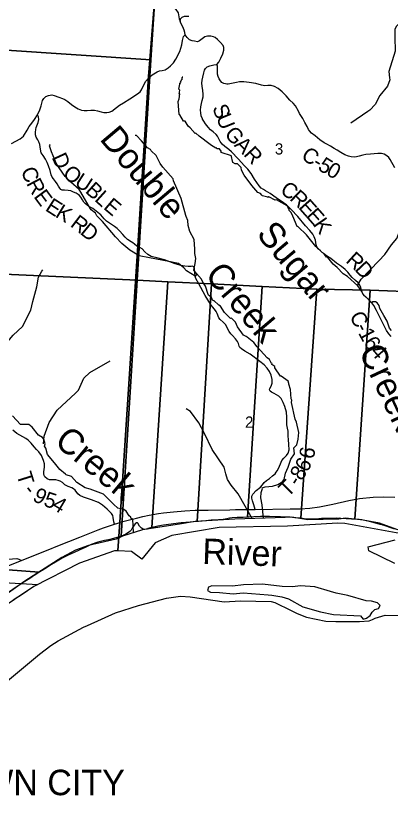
# Model space of a CAD drawing. Extents: x 1878108 to 2183446, y 146837 to 508383.
# Drawn here: x 2033633 to 2040993, y 212319 to 228134 of the extents above; entities that cross this region are included whole.
import ezdxf

# ---------------------------------------------------------------- set-up
doc = ezdxf.new("R2010")
doc.units = 0
for name, color, linetype in [('GM_X_Corporation', 7, 'Continuous'), ('GM_X_Corporation_Text', 7, 'Continuous'), ('GM_X_County', 7, 'Continuous'), ('GM_X_County_Road', 7, 'Continuous'), ('GM_X_County_Road_Text', 7, 'Continuous'), ('GM_X_Major_River', 7, 'Continuous'), ('GM_X_Major_River_Text', 7, 'Continuous'), ('GM_X_Minor_River', 7, 'Continuous'), ('GM_X_Minor_River_Text', 7, 'Continuous'), ('GM_X_Section', 7, 'Continuous'), ('GM_X_Section_Text', 7, 'Continuous'), ('GM_X_State_Route', 7, 'Continuous'), ('GM_X_Township', 7, 'Continuous'), ('GM_X_Township_Road', 7, 'Continuous'), ('GM_X_Township_Road_Text', 7, 'Continuous')]:
    doc.layers.add(name, color=color, linetype=linetype)

msp = doc.modelspace()

# ---------------------------------------------------------------- linework, layer by layer
at = {"layer": 'GM_X_Corporation'}
msp.add_lwpolyline([(2028815, 217287), (2034057, 216976), (2034022, 216959), (2033981, 216937), (2033944, 216913), (2033857, 216855), (2033789, 216810), (2033711, 216759), (2033635, 216707), (2033575, 216668)], dxfattribs=at)
at = {"layer": 'GM_X_County'}
for points in [[(2041168, 217981), (2040086, 218175), (2039954, 218181), (2038960, 218124), (2037622, 218100), (2036688, 217942), (2036361, 217795), (2036102, 217475), (2035896, 217629), (2035631, 217639), (2035563, 217641), (2034879, 217399), (2033979, 216936), (2033237, 216441)], [(2041068, 217391), (2040557, 217640), (2040547, 217716), (2041076, 217853)]]:
    msp.add_lwpolyline(points, dxfattribs=at)
at = {"layer": 'GM_X_County_Road'}
for points in [[(2037577, 227184), (2037613, 227229), (2037653, 227309), (2037694, 227392), (2037713, 227464), (2037711, 227516), (2037698, 227554), (2037648, 227616), (2037586, 227673), (2037541, 227712), (2037507, 227730), (2037460, 227738), (2037392, 227742), (2037338, 227730), (2037286, 227691), (2037236, 227650), (2037193, 227631), (2037136, 227639), (2037089, 227647), (2037039, 227671), (2036989, 227712), (2036956, 227764), (2036944, 227810), (2036935, 227860), (2036923, 227890), (2036904, 227924), (2036869, 227992), (2036853, 228035), (2036868, 228085), (2036897, 228115), (2036941, 228132), (2037023, 228135)], [(2036335, 227002), (2036401, 227041), (2036447, 227058), (2036502, 227067), (2036561, 227080), (2036619, 227117), (2036663, 227157), (2036722, 227215), (2036769, 227288), (2036845, 227438), (2036886, 227573), (2036903, 227657), (2036922, 227733), (2036956, 227764)], [(2037295, 226108), (2037291, 226116), (2037269, 226178), (2037262, 226233), (2037256, 226286), (2037261, 226354), (2037272, 226419), (2037289, 226480), (2037305, 226551), (2037306, 226605), (2037299, 226677), (2037284, 226762), (2037282, 226815), (2037288, 226878), (2037302, 226936), (2037318, 227020), (2037332, 227073), (2037354, 227107), (2037386, 227136), (2037434, 227159), (2037518, 227175), (2037577, 227184)], [(2041070, 225156), (2040978, 225321), (2040953, 225358), (2040916, 225393), (2040863, 225424), (2040807, 225436), (2040734, 225436), (2040590, 225426), (2040502, 225418), (2040442, 225405), (2040369, 225382), (2040318, 225370), (2040274, 225363), (2040213, 225370), (2040159, 225382), (2040087, 225408), (2040009, 225454), (2039937, 225500), (2039877, 225538), (2039809, 225580), (2039734, 225618), (2039681, 225648), (2039596, 225705), (2039504, 225781), (2039437, 225838), (2039397, 225880), (2039374, 225911), (2039346, 225966), (2039306, 226043), (2039262, 226121), (2039201, 226220), (2039178, 226265), (2039118, 226374), (2039075, 226425), (2039011, 226485), (2038934, 226566), (2038860, 226647), (2038779, 226713), (2038707, 226753), (2038645, 226770), (2038575, 226770), (2038515, 226767), (2038451, 226777), (2038343, 226809), (2038208, 226832), (2038104, 226844), (2038064, 226844), (2038021, 226841), (2037958, 226828), (2037863, 226811), (2037798, 226799), (2037768, 226799), (2037743, 226802), (2037709, 226814), (2037675, 226832), (2037645, 226861), (2037620, 226904), (2037604, 226947), (2037591, 226994), (2037587, 227068), (2037591, 227153), (2037577, 227184)], [(2033545, 225636), (2033715, 225728), (2033778, 225780), (2033852, 225894), (2033892, 225968), (2033939, 226033), (2033991, 226104), (2034055, 226199), (2034098, 226295), (2034123, 226374), (2034150, 226477), (2034177, 226520), (2034219, 226554), (2034271, 226575), (2034335, 226586), (2034379, 226578), (2034470, 226544), (2034545, 226520), (2034591, 226499), (2034649, 226460), (2034721, 226398), (2034784, 226352), (2034849, 226313), (2034918, 226289), (2034970, 226278), (2035026, 226284), (2035101, 226288), (2035170, 226286), (2035231, 226275), (2035303, 226254), (2035357, 226245), (2035413, 226242), (2035461, 226247), (2035511, 226267), (2035606, 226338), (2035666, 226383), (2035740, 226432), (2035869, 226509), (2036015, 226609), (2036069, 226648), (2036098, 226687), (2036141, 226785), (2036183, 226860), (2036233, 226918), (2036241, 226926), (2036325, 226996), (2036335, 227002)], [(2040997, 221844), (2040950, 221901), (2040908, 221963), (2040853, 222069), (2040711, 222359), (2040659, 222457), (2040622, 222505), (2040538, 222587), (2040478, 222641), (2040451, 222674), (2040426, 222717), (2040413, 222758), (2040404, 222805), (2040386, 222850), (2040353, 222897), (2040300, 222947), (2040232, 223003), (2040192, 223049), (2040145, 223109), (2040098, 223161), (2040025, 223218), (2039928, 223287), (2039812, 223377), (2039730, 223430), (2039670, 223473), (2039610, 223525), (2039568, 223569), (2039541, 223604), (2039526, 223643), (2039513, 223737), (2039502, 223772), (2039489, 223803), (2039460, 223853), (2039399, 223929), (2039318, 224019), (2039163, 224199), (2039037, 224339), (2038942, 224428), (2038884, 224471), (2038743, 224570), (2038624, 224651), (2038528, 224707), (2038491, 224729), (2038446, 224758), (2038404, 224801), (2038358, 224866), (2038314, 224935), (2038249, 225044), (2038184, 225131), (2038118, 225196), (2037991, 225332), (2037866, 225468), (2037813, 225515), (2037734, 225577), (2037681, 225621), (2037640, 225676), (2037609, 225736), (2037587, 225778), (2037564, 225810), (2037501, 225864), (2037448, 225904), (2037405, 225951), (2037352, 226018), (2037317, 226070), (2037295, 226108)]]:
    msp.add_lwpolyline(points, dxfattribs=at)
at = {"layer": 'GM_X_Major_River'}
msp.add_line((2036117, 218054), (2035721, 217930), dxfattribs=at)
for points in [[(2039969, 218259), (2039361, 218246), (2039046, 218300), (2038916, 218294), (2037928, 218263), (2037151, 218218), (2036843, 218163), (2036117, 218054)], [(2041130, 218050), (2040771, 218184), (2040447, 218240), (2040397, 218248), (2040099, 218279), (2039969, 218259)], [(2035721, 217930), (2035596, 217871), (2035053, 217747), (2034797, 217650), (2034532, 217508), (2033807, 217046), (2033292, 216683)], [(2039919, 216809), (2039806, 216844), (2039497, 216935), (2039215, 216951), (2039063, 216933), (2038860, 216939), (2038472, 216984), (2038097, 216972), (2037883, 216947), (2037478, 216953), (2037410, 216927), (2037390, 216859), (2037448, 216829), (2037630, 216821), (2037895, 216797), (2038095, 216812), (2038582, 216778), (2038654, 216768), (2038852, 216736), (2038982, 216697), (2039267, 216543), (2039609, 216441), (2039869, 216391)], [(2033462, 215086), (2034090, 215611), (2034316, 215784), (2034460, 215872), (2034954, 216139), (2035034, 216175), (2035585, 216422), (2036034, 216563), (2036589, 216708), (2036863, 216748), (2037053, 216736), (2037716, 216639), (2038039, 216655), (2038642, 216642), (2038712, 216628), (2039036, 216470), (2039152, 216408), (2039336, 216339), (2039713, 216259), (2039913, 216249)], [(2039869, 216391), (2040399, 216363), (2040449, 216299), (2040517, 216319), (2040585, 216371), (2040627, 216437), (2040681, 216485), (2040751, 216508), (2040781, 216564), (2040731, 216620), (2040611, 216654), (2040505, 216661), (2040149, 216763), (2039919, 216809)], [(2039913, 216249), (2040379, 216253), (2040568, 216267), (2040630, 216289), (2040684, 216315), (2040882, 216377), (2041258, 216372)]]:
    msp.add_lwpolyline(points, dxfattribs=at)
at = {"layer": 'GM_X_Minor_River'}
for points in [[(2041981, 228997), (2041911, 228963), (2041916, 228744), (2041850, 228620), (2041717, 228488), (2041619, 228427), (2041435, 228298), (2041095, 227930), (2041071, 227871), (2041071, 227721), (2041074, 227444), (2040950, 227047), (2040966, 226922), (2040973, 226882), (2040926, 226761), (2040778, 226577), (2040687, 226400), (2040580, 226287), (2040541, 226260), (2040207, 226032)], [(2037658, 225454), (2037660, 225482), (2037624, 225530), (2037573, 225530), (2037567, 225546), (2037553, 225542), (2037453, 225606), (2037445, 225616), (2037231, 225778), (2037165, 225834), (2037151, 225828), (2037053, 225942), (2037013, 225974), (2036951, 226070), (2036921, 226074), (2036849, 226196), (2036833, 226204), (2036817, 226459), (2036833, 226513), (2036851, 226608), (2036835, 226600), (2036849, 226680), (2036831, 226700), (2036847, 226796), (2036851, 226819), (2036869, 226827), (2036861, 226847), (2036885, 226887), (2036897, 226885), (2036897, 226929), (2036909, 226933), (2036897, 226933)], [(2038491, 218275), (2038465, 218545), (2038441, 218681), (2038443, 218784), (2038473, 218864), (2038465, 218874), (2038525, 218896), (2038666, 218911), (2038770, 218943), (2038858, 218995), (2038868, 219007), (2038898, 219038), (2038922, 219166), (2038973, 219281), (2039029, 219437), (2039099, 219544), (2039089, 219660), (2039143, 219722), (2039172, 219829), (2039182, 219959), (2039142, 220164), (2039110, 220226), (2039042, 220549), (2039050, 220599), (2039034, 220625), (2039020, 220806), (2038986, 220910), (2038986, 220924), (2038978, 220968), (2038840, 221070), (2038826, 221070), (2038714, 221232), (2038714, 221258), (2038658, 221296), (2038662, 221316), (2038646, 221314), (2038610, 221393), (2038560, 221429), (2038366, 221643), (2038301, 221727), (2038169, 221833), (2038151, 221847), (2038097, 221871), (2037979, 222033), (2037939, 222126), (2037861, 222208), (2037845, 222202), (2037793, 222252), (2037727, 222318), (2037649, 222442), (2037613, 222460), (2037513, 222550), (2037499, 222548), (2037467, 222614), (2037411, 222656), (2037403, 222670), (2037351, 222833), (2037309, 222897), (2037273, 222971), (2037174, 223079), (2037126, 223147), (2037151, 223276), (2037165, 223378), (2037143, 223476), (2037145, 223560), (2037129, 223751), (2037043, 223907), (2037011, 224022), (2037003, 224120), (2036971, 224204), (2036963, 224220), (2036873, 224553), (2036721, 224900), (2036715, 224940), (2036511, 225170), (2036465, 225244), (2036381, 225397), (2036285, 225489), (2036275, 225519), (2036215, 225551), (2036093, 225685), (2036000, 225793), (2035974, 225793)], [(2037185, 223067), (2037150, 223027), (2036982, 223137), (2036926, 223191), (2036822, 223279), (2036634, 223318), (2036251, 223388), (2036052, 223426), (2035864, 223543), (2035712, 223668), (2035586, 223804), (2035328, 224104), (2035221, 224212), (2035191, 224264), (2035105, 224332), (2035093, 224350), (2034903, 224681), (2034871, 224729), (2034707, 224873), (2034659, 224903), (2034643, 224941), (2034593, 224983), (2034481, 225158), (2034423, 225232), (2034329, 225470), (2034291, 225587), (2034299, 225603), (2034291, 225613)], [(2037860, 225392), (2037658, 225454)], [(2041005, 221962), (2040969, 222012), (2040923, 222146), (2040855, 222257), (2040773, 222397), (2040763, 222455), (2040725, 222505), (2040691, 222523), (2040639, 222529), (2040615, 222509), (2040505, 222619), (2040447, 222671), (2040423, 222729), (2040341, 222841), (2040142, 223021), (2040054, 223077), (2039936, 223202), (2039860, 223264), (2039756, 223394), (2039730, 223404), (2039692, 223458), (2039530, 223602), (2039522, 223612), (2039333, 223840), (2039171, 223996), (2039151, 224004), (2039069, 224205), (2039033, 224281), (2038993, 224319), (2038995, 224345), (2038967, 224387), (2038955, 224411), (2038745, 224525), (2038723, 224519), (2038597, 224587), (2038577, 224571), (2038577, 224583), (2038474, 224607), (2038458, 224619), (2038434, 224649), (2038380, 224675), (2038264, 224809), (2038114, 225015), (2038058, 225112), (2038054, 225164), (2037978, 225234), (2037934, 225236), (2037890, 225260), (2037858, 225402), (2037856, 225403)], [(2040338, 222841), (2040344, 222862), (2040411, 222968), (2040754, 223330), (2040875, 223457), (2041003, 223645), (2041110, 223772), (2041197, 223994), (2041203, 224184)], [(2033390, 221597), (2033403, 221671), (2033572, 221872), (2033755, 222041), (2033923, 222364), (2033958, 222533), (2034042, 222819), (2034074, 223013), (2034139, 223125), (2034158, 223154)], [(2034171, 219741), (2034182, 219888), (2034284, 220155), (2034440, 220400), (2034797, 220736), (2034855, 220794), (2034961, 221027), (2035079, 221137), (2035479, 221365)], [(2038267, 218275), (2037996, 218756), (2037853, 218928), (2037785, 219038), (2037751, 219150), (2037722, 219279), (2037483, 219625), (2037334, 219944), (2037218, 220148), (2037059, 220371), (2036971, 220429)], [(2035935, 217999), (2035926, 218258), (2035885, 218282), (2035885, 218302), (2035853, 218324), (2035791, 218416), (2035747, 218452), (2035629, 218474), (2035545, 218554), (2035347, 218753), (2035090, 218848), (2034992, 218878), (2034828, 218978), (2034718, 219100), (2034614, 219132), (2034600, 219144), (2034490, 219238), (2034385, 219368), (2034247, 219533), (2034219, 219655), (2034191, 219691), (2034203, 219739), (2034175, 219829), (2034149, 219861), (2034071, 219909), (2033947, 220068), (2033883, 220120), (2033733, 220121), (2033717, 220117), (2033561, 220290)]]:
    msp.add_lwpolyline(points, dxfattribs=at)
at = {"layer": 'GM_X_Section'}
for points in [[(2036357, 228504), (2036355, 228477), (2036280, 227277), (2033343, 227475), (2030822, 227644), (2030910, 228899)], [(2036355, 228477), (2041943, 228267), (2041598, 222717), (2040585, 222757), (2039540, 222774), (2038466, 222827), (2037467, 222878), (2036610, 222920), (2036010, 222952), (2036280, 227277)], [(2036280, 227277), (2036010, 222952), (2033099, 223082), (2033343, 227475)], [(2036010, 222952), (2036610, 222920), (2036299, 218096), (2036244, 218083), (2036228, 218077), (2036206, 218067), (2036188, 218065), (2036156, 218061), (2036126, 218067), (2036094, 218085), (2036058, 218123), (2036022, 218179), (2036014, 218191), (2036006, 218191), (2035994, 218189), (2035972, 218169), (2035950, 218141), (2035914, 218083), (2035890, 218046), (2035868, 218020), (2035840, 217998), (2035806, 217976), (2035766, 217956), (2035741, 217944), (2035733, 217940), (2035699, 217926)], [(2036610, 222920), (2037467, 222878), (2037190, 218215), (2037054, 218203), (2036874, 218187), (2036526, 218140), (2036416, 218120), (2036364, 218107), (2036299, 218096)], [(2037467, 222878), (2038466, 222827), (2038179, 218300), (2038090, 218295), (2037972, 218291), (2037876, 218287), (2037824, 218279), (2037774, 218265), (2037700, 218254), (2037662, 218248), (2037606, 218246), (2037466, 218238), (2037356, 218230), (2037212, 218217), (2037190, 218215)], [(2038466, 222827), (2039540, 222774), (2039225, 218277), (2039105, 218289), (2039017, 218297), (2038951, 218303), (2038915, 218303), (2038823, 218307), (2038729, 218309), (2038609, 218310), (2038519, 218314), (2038431, 218310), (2038304, 218306), (2038212, 218301), (2038179, 218300)], [(2039540, 222774), (2040585, 222757), (2040285, 218260), (2040221, 218261), (2040012, 218273), (2039986, 218277), (2039973, 218273), (2039931, 218277), (2039837, 218273), (2039759, 218273), (2039717, 218275), (2039629, 218271), (2039577, 218266), (2039477, 218262), (2039389, 218260), (2039293, 218270), (2039225, 218277)], [(2040585, 222757), (2041598, 222717), (2041284, 218009), (2041232, 218025), (2041142, 218049), (2041049, 218074), (2040989, 218090), (2040881, 218130), (2040837, 218146), (2040809, 218153), (2040783, 218155), (2040761, 218163), (2040689, 218185), (2040619, 218203), (2040573, 218215), (2040507, 218228), (2040423, 218248), (2040369, 218254), (2040285, 218260)], [(2030162, 217516), (2034088, 217218), (2034042, 217188), (2033990, 217154), (2033950, 217128), (2033902, 217094), (2033802, 217034), (2033652, 216939), (2033568, 216879), (2033484, 216819), (2033376, 216729), (2033342, 216699), (2033259, 216642), (2033193, 216590), (2033139, 216538), (2033069, 216456), (2033031, 216422), (2032929, 216350), (2032859, 216299), (2032811, 216259), (2030073, 216405)]]:
    msp.add_lwpolyline(points, close=True, dxfattribs=at)
msp.add_lwpolyline([(2033099, 223082), (2036010, 222952), (2035699, 217926), (2035657, 217912), (2035545, 217880), (2035445, 217857), (2035367, 217843), (2035237, 217809), (2035107, 217761), (2035003, 217714), (2034871, 217652), (2034773, 217606), (2034655, 217554), (2034539, 217497), (2034471, 217457), (2034407, 217419), (2034329, 217371), (2034251, 217321), (2034143, 217256), (2034100, 217228), (2034088, 217218), (2030162, 217516)], dxfattribs=at)
at = {"layer": 'GM_X_State_Route'}
for points in [[(2038276, 218451), (2038328, 218452), (2039013, 218463), (2039209, 218466), (2039403, 218477), (2039593, 218500), (2039856, 218555), (2040165, 218626), (2040375, 218663), (2040643, 218690), (2040857, 218697), (2041070, 218694)], [(2035409, 218113), (2035564, 218165), (2035632, 218184), (2035667, 218195), (2035703, 218207), (2035834, 218243), (2035996, 218283), (2036122, 218311), (2036244, 218337), (2036319, 218349), (2036427, 218370), (2036528, 218383), (2036721, 218407), (2036944, 218427), (2037152, 218435), (2037407, 218440), (2037828, 218447), (2037944, 218448), (2037966, 218448)], [(2037966, 218448), (2038259, 218451), (2038276, 218451)], [(2032768, 217063), (2032896, 217116), (2033327, 217288), (2033736, 217450), (2034076, 217585), (2034261, 217657), (2034454, 217737), (2034886, 217908), (2035242, 218048), (2035352, 218093), (2035409, 218113)]]:
    msp.add_lwpolyline(points, dxfattribs=at)
at = {"layer": 'GM_X_Township'}
for points in [[(2041168, 217981), (2040086, 218175), (2039954, 218181), (2038960, 218124), (2037622, 218100), (2036688, 217942), (2036361, 217795), (2036102, 217475), (2035896, 217629), (2035631, 217639), (2035667, 218204), (2036020, 223625), (2036235, 226946), (2036351, 228419), (2036493, 230741), (2036623, 232849), (2036687, 233905), (2036924, 237810), (2037025, 239474), (2037219, 242509), (2037354, 244623), (2042339, 244401)], [(2036351, 228419), (2036235, 226946), (2036020, 223625), (2035667, 218204), (2035631, 217639), (2035563, 217641), (2034879, 217399), (2033979, 216936), (2033237, 216441), (2032405, 215615), (2031983, 215029), (2031661, 214693), (2031514, 214360), (2030991, 213776), (2029856, 212824), (2029251, 212319), (2027533, 212388), (2026592, 212426), (2022114, 212606), (2015261, 212882)], [(2041068, 217391), (2040557, 217640), (2040547, 217716), (2041076, 217853)]]:
    msp.add_lwpolyline(points, dxfattribs=at)
at = {"layer": 'GM_X_Township_Road'}
for points in [[(2036327, 228408), (2036342, 228412), (2036350, 228413), (2036426, 228424), (2036496, 228419), (2036576, 228401), (2036643, 228375), (2036691, 228341), (2036769, 228261), (2036814, 228201), (2036838, 228083), (2036853, 228035)], [(2035922, 223681), (2035891, 223705), (2035823, 223752), (2035776, 223795), (2035729, 223848), (2035661, 223922), (2035618, 223965), (2035566, 224004), (2035504, 224046), (2035444, 224081), (2035411, 224109), (2035361, 224156), (2035299, 224231), (2035271, 224256), (2035204, 224305), (2035138, 224355), (2035058, 224400), (2034993, 224447), (2034963, 224483), (2034936, 224529), (2034907, 224582), (2034880, 224612), (2034853, 224635), (2034812, 224658), (2034762, 224679), (2034705, 224705), (2034652, 224713), (2034585, 224715), (2034538, 224718), (2034513, 224733), (2034490, 224756), (2034465, 224793), (2034437, 224839), (2034403, 224890), (2034365, 224940), (2034340, 224972), (2034318, 225019), (2034299, 225101), (2034269, 225198), (2034241, 225259), (2034209, 225323), (2034164, 225395), (2034127, 225453), (2034112, 225521), (2034096, 225615), (2034082, 225663), (2034060, 225704), (2034029, 225761), (2034014, 225806), (2034013, 225859), (2034018, 225911), (2034026, 225947), (2034068, 226046), (2034081, 226106), (2034072, 226155), (2034055, 226199)], [(2038741, 219182), (2038761, 219208), (2038786, 219258), (2038822, 219347), (2038851, 219412), (2038893, 219459), (2038943, 219508), (2038978, 219555), (2038997, 219619), (2038991, 219724), (2038979, 219827), (2038977, 219892), (2038977, 219990), (2038963, 220049), (2038950, 220113), (2038950, 220176), (2038952, 220265), (2038940, 220358), (2038910, 220469), (2038880, 220553), (2038840, 220626), (2038790, 220672), (2038700, 220724), (2038649, 220755), (2038622, 220776), (2038611, 220802), (2038616, 220825), (2038642, 220869), (2038662, 220930), (2038660, 221000), (2038643, 221084), (2038612, 221159), (2038565, 221225), (2038502, 221291), (2038421, 221354), (2038229, 221500), (2038127, 221559), (2038056, 221601), (2038025, 221627), (2038014, 221655), (2038000, 221707), (2037979, 221749), (2037941, 221801), (2037880, 221866), (2037848, 221900), (2037814, 221946), (2037772, 222032), (2037749, 222072), (2037699, 222126), (2037640, 222179), (2037613, 222215), (2037583, 222294), (2037560, 222338), (2037530, 222380), (2037491, 222427), (2037452, 222480), (2037347, 222650), (2037224, 222881), (2037164, 222983), (2037148, 223033), (2037140, 223097), (2037137, 223182), (2037126, 223208), (2037105, 223223), (2037072, 223220), (2037015, 223219), (2036946, 223227), (2036871, 223241), (2036757, 223271), (2036544, 223349), (2036397, 223388), (2036284, 223418), (2036217, 223457), (2036159, 223507), (2036106, 223564), (2036060, 223592), (2036019, 223613), (2036004, 223620), (2035956, 223655), (2035922, 223681)], [(2035564, 218165), (2035549, 218208), (2035537, 218294), (2035529, 218332), (2035504, 218374), (2035421, 218460), (2035331, 218537), (2035248, 218588), (2035113, 218638), (2034957, 218691), (2034887, 218724), (2034847, 218760), (2034795, 218828), (2034762, 218858), (2034728, 218877), (2034654, 218901), (2034591, 218937), (2034544, 218979), (2034498, 219008), (2034460, 219021), (2034412, 219031), (2034350, 219030), (2034287, 219031), (2034245, 219053), (2034198, 219094), (2034186, 219116), (2034174, 219150), (2034174, 219187), (2034190, 219284), (2034187, 219347), (2034173, 219413), (2034132, 219508), (2034076, 219581), (2034030, 219631), (2033986, 219681), (2033927, 219752), (2033869, 219808), (2033826, 219844), (2033765, 219879), (2033650, 219943), (2033565, 220009)], [(2038469, 218937), (2038507, 218983), (2038551, 219022), (2038606, 219058), (2038669, 219108), (2038719, 219153), (2038741, 219182)], [(2038328, 218452), (2038299, 218539), (2038272, 218618), (2038260, 218674), (2038263, 218711), (2038285, 218753), (2038350, 218825), (2038431, 218891), (2038469, 218937)], [(2032928, 217424), (2033060, 217448), (2033183, 217468), (2033325, 217477), (2033563, 217479), (2033645, 217486), (2033688, 217476), (2033736, 217450)]]:
    msp.add_lwpolyline(points, dxfattribs=at)

# ---------------------------------------------------------------- texts
at = {"layer": 'GM_X_Corporation_Text'}
msp.add_text('CROWN CITY', height=500, rotation=0, dxfattribs=at).set_placement((2031460, 212843))
at = {"layer": 'GM_X_County_Road_Text'}
for s, rotation, p in [('S', 291.8041, (2037480, 226336)), ('U', 292.1717, (2037556, 226147)), ('G', 310.484, (2037710, 225813)), ('A', 315.4554, (2037901, 225591)), ('R', 312.8248, (2038086, 225409)), ('C', 324.0746, (2039211, 225353)), ('5', 328.8546, (2039540, 225129)), ('-', 329.0458, (2039435, 225192)), ('0', 330.4203, (2039706, 225029)), ('C', 324.0036, (2038798, 224677)), ('R', 316.4353, (2038989, 224539)), ('E', 311.5826, (2039163, 224374)), ('E', 311.267, (2039312, 224207)), ('K', 304.6035, (2039454, 224045)), ('R', 317.7996, (2040090, 223315)), ('D', 313.3796, (2040268, 223154)), ('C', 297.5557, (2040172, 222247)), ('-', 297.6185, (2040286, 222028)), ('1', 297.852, (2040344, 221918)), ('6', 302.5796, (2040444, 221731)), ('4', 311.2111, (2040573, 221536))]:
    msp.add_text(s, height=300, rotation=rotation, dxfattribs=at).set_placement(p)
at = {"layer": 'GM_X_Major_River_Text'}
msp.add_text('River', height=500, rotation=357.9954, dxfattribs=at).set_placement((2037283, 217384))
at = {"layer": 'GM_X_Minor_River_Text'}
for s, rotation, p in [('Double', 310.1353, (2035257, 225716)), ('Sugar', 310.1349, (2038336, 223846)), ('Creek', 310.135, (2037323, 223044)), ('Creek', 295.1343, (2040354, 221561)), ('Creek', 320.1349, (2034360, 219747))]:
    msp.add_text(s, height=500, rotation=rotation, dxfattribs=at).set_placement(p)
at = {"layer": 'GM_X_Section_Text'}
for s, p in [('3', (2038715, 225417)), ('2', (2038129, 220055))]:
    msp.add_text(s, height=221, rotation=0, dxfattribs=at).set_placement(p)
at = {"layer": 'GM_X_Township_Road_Text'}
for s, rotation, p in [('D', 294.7141, (2034325, 225365)), ('C', 293.4802, (2033718, 225099)), ('O', 321.3458, (2034528, 225006)), ('U', 327.1464, (2034761, 224822)), ('R', 297.6571, (2033827, 224852)), ('B', 317.7636, (2034973, 224686)), ('E', 306.3456, (2033967, 224591)), ('E', 327.3764, (2034187, 224329)), ('L', 318.0924, (2035157, 224520)), ('E', 319.7162, (2035331, 224364)), ('K', 328.9222, (2034384, 224203)), ('R', 322.7648, (2034679, 224019)), ('D', 320.9272, (2034873, 223871)), ('6', 79.4082, (2039477, 219427)), ('6', 59.6752, (2039345, 219163)), ('T', 287.3731, (2033637, 219137)), ('8', 58.1295, (2039243, 218998)), ('T', 44.6773, (2038969, 218677)), ('-', 57.3982, (2039174, 218891)), ('-', 308.0893, (2033758, 218819)), ('9', 331.8752, (2033938, 218635)), ('5', 342.2489, (2034155, 218525)), ('4', 329.0438, (2034315, 218476))]:
    msp.add_text(s, height=300, rotation=rotation, dxfattribs=at).set_placement(p)

doc.saveas('drawing.dxf')
